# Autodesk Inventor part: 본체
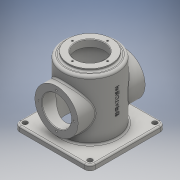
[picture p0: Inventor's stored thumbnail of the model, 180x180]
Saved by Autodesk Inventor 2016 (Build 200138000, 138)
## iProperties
Created: 2019-08
Part Number: 본체
Material: 일반
Document SubType Name: Modeling
Designer: user
Density: 1 g/cm^3
Appearance: 기본값
Author: user
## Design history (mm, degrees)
sketch "스케치1"
  geometry: L1 (70, -70)-(-70, -70); L2 (-70, -70)-(-70, 70); L3 (-70, 70)-(70, 70); L4 (70, 70)-(70, -70); L5 (70, -70)-(-70, 70); L6 (-70, -70)-(70, 70); 1 further point
  constraints: 12 end point, 2 midpoint, 2 parallel, 1 horizontal, 1 perpendicular
  dimensions: "d0" = 140 distance of L2.end L3.end; "d1" = 140 distance of L1.end L2.end
extrude "돌출1" new body sketch "스케치1" distance "d2" = 10; taper "d3" = 0 deg
sketch "스케치2"
  geometry: C1 r 50 at (0, 0); 1 further point
  constraints: 1 centre point, 1 coincident
  dimensions: "d4" = 100 diameter of C1
extrude "돌출2" join sketch "스케치2" distance "d5" = 110; taper "d6" = 0 deg
sketch "스케치3"
  geometry: C1 r 45 at (0, 0); 1 further point
  constraints: 1 centre point, 1 coincident
  dimensions: "d7" = 90 diameter of C1
extrude "돌출3" cut sketch "스케치3" distance "d8" = 112; taper "d9" = 0 deg
sketch "스케치4"
  geometry: C1 r 40 at (0, 0); 1 further point
  constraints: 1 centre point, 1 coincident
  dimensions: "d10" = 80 diameter of C1
extrude "돌출4" join sketch "스케치4" distance "d11" = 5; taper "d12" = 0 deg
node "작업 평면1"
sketch "스케치6"
  geometry: L1 (-70, 0)-(70, 0) reference; C1 r 40 at (0, 60); 2 further points
  constraints: 1 centre point, 1 midpoint, 1 vertical alignment
  dimensions: "d14" = 80 diameter of C1; "d15" = 60 distance from line of L1 C1.centre
extrude "돌출5" join sketch "스케치6" stored distance "d16" = 5; taper "d17" = 0 deg
hole "구멍1" diameter "d20" = 54; stored, may be unused: countersink angle "d24" = 90 deg, drill point angle "d26" = 118 deg; dims "d18" = 10, "d19" = 10, "d21" = 6, "d22" = 4, "d23" = 2, "d25" = 8
sketch "스케치7"
  geometry: C1 r 27 at (0, 0); 1 further point
  constraints: 1 centre point, 1 coincident
  dimensions: "d27" = 54 diameter of C1
extrude "돌출6" cut sketch "스케치7" distance "d28" = 13; taper "d29" = 0 deg
fillet "모깎기1" dims "d30" = 5
sketch "스케치8"
  geometry: 2 further points
  constraints: 1 vertical alignment
  dimensions: "d31" = 32.5 distance of point (0, 0) point (0, 32.5)
hole "구멍2" sketch "스케치8" at (0, 32.5) diameter "d32" = 3.242; stored, may be unused: countersink angle "d36" = 90 deg, drill point angle "d38" = 118 deg; dims "d33" = 8, "d34" = 4, "d35" = 2, "d37" = 10
sketch "스케치9"
  geometry: C1 r 27 at (0, 0) reference; 2 further points
  constraints: 1 vertical alignment
  dimensions: "d42" = 32.5 distance of C1.centre point (0, 32.5)
hole "구멍3" sketch "스케치9" at (0, 32.5) diameter "d43" = 3.242; stored, may be unused: countersink angle "d47" = 90 deg, drill point angle "d49" = 118 deg; dims "d44" = 8, "d45" = 4, "d46" = 2, "d48" = 10
chamfer "모따기1" distance "d53" = 1; stored, may be unused: second distance "d54" = 2, angle "d55" = 45 deg
chamfer "모따기2" distance "d56" = 1; stored, may be unused: second distance "d57" = 2, angle "d58" = 45 deg
fillet "모깎기2" dims "d59" = 10
hole "구멍4" diameter "d62" = 9; stored, may be unused: countersink angle "d66" = 90 deg, drill point angle "d68" = 0 deg; dims "d60" = 10, "d61" = 10, "d63" = 8, "d64" = 4, "d65" = 2, "d67" = 10
hole "구멍5" diameter "d71" = 9; stored, may be unused: countersink angle "d75" = 90 deg, drill point angle "d77" = 0 deg; dims "d69" = 10, "d70" = 10, "d72" = 8, "d73" = 4, "d74" = 2, "d76" = 10
fillet "모깎기3" dims "d78" = 3
fillet "모깎기4" dims "d79" = 3
fillet "모깎기5" dims "d80" = 3
fillet "모깎기6" dims "d81" = 3
node "작업 평면2"
sketch "스케치13" dims "d0" = 140, "d1" = 140, "d10" = 80
  geometry: L1 (60, 0)-(-60, 0) reference; 3 further points
  constraints: 1 midpoint, 1 vertical alignment, 1 other
  dimensions: "d83" = 70 distance from line of L1 point (0, 70)
feature "엠보싱1" sketch "스케치13" dims "d10" = 80, "d84" = 0.5, "d85" = 0
fillet "모깎기7" dims "d86" = 3
node "솔리드1"
mirror "대칭1"
pattern_circular "원형 패턴1" dims angle "d40" = 360 deg
pattern_circular "원형 패턴2" dims angle "d51" = 360 deg
mirror "대칭2"
mirror "대칭3"
other parameters: "d13" = -62, "d82" = 54.25
